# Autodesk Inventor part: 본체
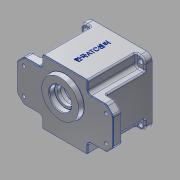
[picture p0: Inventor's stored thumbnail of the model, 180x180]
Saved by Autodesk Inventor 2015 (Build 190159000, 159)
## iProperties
Created: 2016-02
Part Number: 본체
Material: Aluminum 6061
Document SubType Name: Modeling
Designer: Administrator
Density: 2.7 g/cm^3
Appearance: Aluminum - Flat
Mass: 873.756 g
Surface Area: 761.195 cm^2
Volume: 323.613 cm^3
Author: Administrator
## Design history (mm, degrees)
sketch "Sketch2"
  geometry: L1 (-33, 30)-(-33, 47); L2 (-33, 47)-(33, 47); L3 (33, 47)-(33, 30); L4 (33, 30)-(57.929, 30); L5 (70, 17.929)-(70, -17.929); L6 (57.929, -30)-(33, -30); L7 (33, -30)-(33, -47); L8 (33, -47)-(-33, -47); L9 (-33, -47)-(-33, -30); L10 (-33, -30)-(-57.929, -30); L11 (-70, -17.929)-(-70, 17.929); L12 (-57.929, 30)-(-33, 30); L13 (-68.536, 21.464)-(-61.464, 28.536); L14 (-68.536, -21.464)-(-61.464, -28.536); L15 (61.464, -28.536)-(68.536, -21.464); L16 (68.536, 21.464)-(61.464, 28.536); A1 r 5 centre (57.929, -25) between (57.929, -30) and (61.464, -28.536); A2 r 5 centre (65, -17.929) between (68.536, -21.464) and (70, -17.929); A3 r 5 centre (65, -17.929) between (68.536, -21.464) and (70, -17.929); A4 r 5 centre (65, 17.929) between (70, 17.929) and (68.536, 21.464); A5 r 5 centre (57.929, 25) between (61.464, 28.536) and (57.929, 30); A6 r 5 centre (-57.929, 25) between (-57.929, 30) and (-61.464, 28.536); A7 r 5 centre (-65, 17.929) between (-68.536, 21.464) and (-70, 17.929); A8 r 5 centre (-57.929, -25) between (-61.464, -28.536) and (-57.929, -30); A9 r 5 centre (-65, -17.929) between (-70, -17.929) and (-68.536, -21.464); 13 further points
  constraints: 32 end point, 26 point on line, 18 point on circle, 18 tangent, 11 perpendicular, 9 centre point, 8 equal radius, 1 vertical
  dimensions: "d8" = 66 distance between parallel lines of L3 L1; "d9" = 66 distance between parallel lines of L7 L9; "d10" = 33 distance from line of point (0, 0) L1; "d11" = 33 distance from line of point (0, 0) L9; "d12" = 60 distance between parallel lines of L6 L4; "d13" = 60 distance of point (-70, -30) point (-70, 30); "d14" = 30 distance from line of point (0, 0) L12; "d15" = 30 distance from line of point (0, 0) L4; "d16" = 94 distance between parallel lines of L8 L2; "d17" = 47 distance from line of point (0, 0) L2; "d18" = 140 distance between parallel lines of L5 L11; "d19" = 70 distance from line of point (0, 0) L11; "d20" = 10 distance of point (-70, 20) point (-70, 30); "d21" = 10 distance of point (-60, 30) point (-70, 30) (= d20); "d22" = 10 distance of point (-70, -20) point (-70, -30) (= d20); "d23" = 10 distance of point (-60, -30) point (-70, -30) (= d22); "d24" = 10 distance of point (60, -30) point (70, -30) (= d20); "d25" = 10 distance of point (70, -20) point (70, -30) (= d24); "d26" = 10 distance of point (70, 20) point (70, 30) (= d20); "d27" = 10 distance of point (60, 30) point (70, 30) (= d26); "d127" = 5 radius of A1
extrude "Extrusion1" new body sketch "Sketch2" distance "d28" = 13; taper "d29" = 0 deg
sketch "Sketch3"
  geometry: L1 (39, 47)-(-39, 47); L2 (-47, 39)-(-47, -39); L3 (-39, -47)-(39, -47); L4 (47, -39)-(47, 39); L5 (47, 47)-(-47, -47); L6 (-47, 47)-(47, -47); A1 r 8 centre (39, -39) between (39, -47) and (47, -39); A2 r 8 centre (39, 39) between (47, 39) and (39, 47); A3 r 8 centre (-39, 39) between (-39, 47) and (-47, 39); A4 r 8 centre (-39, -39) between (-47, -39) and (-39, -47); 1 further point
  constraints: 12 end point, 8 point on circle, 8 point on line, 8 tangent, 4 centre point, 3 equal radius, 2 midpoint, 2 parallel, 1 horizontal, 1 perpendicular
  dimensions: "d30" = 94 distance of L5.end L6.end; "d31" = 94 distance of L6.start L5.end; "d32" = 8 radius of A1
extrude "Extrusion2" join sketch "Sketch3" distance "d33" = 67; taper "d34" = 0 deg
sketch "Sketch4"
  geometry: L1 (33, 30)-(47, 30) reference; L2 (47, 30)-(47, 39) reference; L3 (39, 47)-(33, 47) reference; L4 (33, 47)-(33, 30) reference; L5 (-47, 30)-(-33, 30) reference; L6 (-33, 30)-(-33, 47) reference; L7 (-33, 47)-(-39, 47) reference; L8 (-47, 39)-(-47, 30) reference; L9 (-33, -47)-(-33, -30) reference; L10 (-33, -30)-(-47, -30) reference; L11 (-47, -30)-(-47, -39) reference; L12 (-39, -47)-(-33, -47) reference; L13 (33, -30)-(33, -47) reference; L14 (33, -47)-(39, -47) reference; L15 (47, -39)-(47, -30) reference; L16 (47, -30)-(33, -30) reference; A1 r 8 centre (39, 39) between (47, 39) and (39, 47) reference; A2 r 8 centre (-39, 39) between (-39, 47) and (-47, 39) reference; A3 r 8 centre (-39, -39) between (-47, -39) and (-39, -47) reference; A4 r 8 centre (39, -39) between (39, -47) and (47, -39) reference; 1 further point
extrude "Extrusion3" cut sketch "Sketch4" distance "d35" = 57; taper "d36" = 0 deg
sketch "Sketch5"
  geometry: A1 r 36 centre (0, 0) between (-36, 0) and (36, 0); A2 r 4 centre (36, 0) between (35.852, 3.997) and (35.852, -3.997); A3 r 4 centre (-36, 0) between (-35.852, -3.997) and (-35.852, 3.997); A4 r 3.5 centre (35.722, -7.495) between (39.148, -8.214) and (35.778, -3.995); A5 r 3.5 centre (35.722, 7.495) between (35.778, 3.995) and (39.088, 8.456); A6 r 3.5 centre (-35.722, -7.495) between (-35.778, -3.995) and (-39.148, -8.214); A7 r 3.5 centre (-35.722, 7.495) between (-39.148, 8.214) and (-35.778, 3.995); A8 r 40 centre (0, 0) between (39.148, 8.214) and (-39.148, 8.214); A9 r 40 centre (0, 0) between (-39.148, -8.214) and (39.148, -8.214); 1 further point
  constraints: 27 point on circle, 9 centre point, 8 tangent, 2 coincident, 2 horizontal alignment
  dimensions: "d53" = 72 diameter of A1; "d54" = 4 radius of A2; "d55" = 4 radius of A3; "d56" = 3.5 radius of A4; "d57" = 3.5 radius of A5; "d58" = 3.5 radius of A6; "d60" = 40 radius of A9; "d61" = 40 radius of A8; "d62" = 3.5 radius of A7
extrude "Extrusion4" cut sketch "Sketch5" distance "d38" = 71; taper "d39" = 0 deg
sketch "Sketch6"
  geometry: C1 r 28 at (0, 11); 1 further point
  constraints: 1 centre point, 1 vertical alignment
  dimensions: "d40" = 56 diameter of C1; "d41" = 11 distance of point (0, 0) C1.centre
extrude "Extrusion5" join sketch "Sketch6" distance "d42" = 7; taper "d43" = -10 deg
sketch "Sketch10"
  geometry: C1 r 43 at (0, 0); 1 further point
  constraints: 1 centre point, 1 coincident
  dimensions: "d50" = 86 diameter of C1
extrude "Extrusion7" cut sketch "Sketch10" distance "d51" = 9; taper "d52" = 0 deg
sketch "Sketch11"
  geometry: A1 r 4 centre (36, 0) between (35.852, 3.997) and (35.852, -3.997) reference; A2 r 4 centre (-36, 0) between (-35.852, -3.997) and (-35.852, 3.997) reference; 3 further points
  constraints: 2 coincident
hole "Hole1" sketch "Sketch11" at (36, 0), (-36, 0) diameter "d63" = 3.242; stored, may be unused: countersink angle "d67" = 90 deg, drill point angle "d69" = 118 deg; dims "d64" = 7, "d65" = 4, "d66" = 2, "d68" = 9
sketch "Sketch12"
  geometry: C1 r 26.766 at (0, -11) reference; C2 r 21 at (0, -11); C3 r 15 at (0, 20); 1 further point
  constraints: 2 centre point, 1 coincident, 1 vertical alignment
  dimensions: "d72" = 21 radius of C2; "d73" = 15 radius of C3; "d74" = 20 distance of C3.centre point (0, 0)
extrude "Extrusion8" join sketch "Sketch12" distance "d75" = 7; taper "d76" = 0 deg
sketch "Sketch13"
  geometry: A1 r 15 centre (0, 20) between (8.978, 7.984) and (-8.978, 7.984) reference; 2 further points
  constraints: 1 coincident
hole "Hole2" sketch "Sketch13" at (0, 20) diameter "d77" = 19; stored, may be unused: countersink angle "d81" = 90 deg, drill point angle "d83" = 0 deg; dims "d78" = 7, "d79" = 22, "d80" = 7, "d82" = 8
sketch "Sketch14"
  geometry: A1 r 21 centre (0, -11) between (-8.978, 7.984) and (8.978, 7.984) reference; 2 further points
  constraints: 1 coincident
hole "Hole3" sketch "Sketch14" at (0, -11) diameter "d84" = 25; stored, may be unused: countersink angle "d88" = 90 deg, drill point angle "d90" = 0 deg; dims "d85" = 7, "d86" = 35, "d87" = 10, "d89" = 15
sketch "Sketch15"
  geometry: C1 r 26.766 at (0, 0) reference; 2 further points
  constraints: 1 coincident
hole "Hole4" sketch "Sketch15" at (0, 0) diameter "d91" = 32; stored, may be unused: countersink angle "d95" = 90 deg, drill point angle "d97" = 0 deg; dims "d92" = 7, "d93" = 35, "d94" = 10, "d96" = 8
sketch "Sketch17"
  geometry: 5 further points
  constraints: 2 horizontal alignment, 2 vertical alignment
  dimensions: "d102" = 120 distance of point (-60, -19) point (60, -19); "d103" = 60 horizontal distance of point (0, 0) point (60, -19); "d104" = 38 distance of point (-60, 19) point (-60, -19); "d105" = 19 vertical distance of point (0, 0) point (-60, -19)
hole "Hole5" sketch "Sketch17" at (60, -19), (60, 19), (-60, -19), (-60, 19) diameter "d106" = 5; stored, may be unused: countersink angle "d110" = 90 deg, drill point angle "d112" = 0 deg; dims "d107" = 7, "d108" = 9, "d109" = 4, "d111" = 8
sketch "Sketch18"
  geometry: 5 further points
  constraints: 2 horizontal alignment, 2 vertical alignment
  dimensions: "d113" = 80 distance of point (40, 40) point (-40, 40); "d114" = 40 horizontal distance of point (0, 0) point (-40, 40); "d115" = 80 distance of point (40, -40) point (40, 40); "d116" = 40 horizontal distance of point (0, 0) point (40, 40)
hole "Hole6" sketch "Sketch18" at (-40, 40), (-40, -40), (40, 40), (40, -40) diameter "d117" = 7; stored, may be unused: countersink angle "d121" = 90 deg, drill point angle "d123" = 0 deg; dims "d118" = 7, "d119" = 9, "d120" = 4, "d122" = 8
sketch "Sketch19" dims "d8" = 66, "d9" = 66, "d10" = 33, "d11" = 33, "d12" = 60, "d13" = 60, "d14" = 30, "d15" = 30, "d16" = 94, "d17" = 47, "d18" = 140, "d19" = 70, "d20" = 10, "d21" = 10 (= d20), "d22" = 10 (= d20), "d23" = 10 (= d22), "d24" = 10 (= d20), "d25" = 10 (= d24), "d26" = 10 (= d20), "d27" = 10 (= d26), "d127" = 5
  geometry: L1 (0, 0)-(66, 0) reference; L2 (-6, 80)-(72, 80) reference; 3 further points
  constraints: 1 midpoint, 1 vertical alignment, 1 other
  dimensions: "d124" = 40 distance from line of L2 point (33, 40)
emboss "Emboss1" sketch "Sketch19" dims "d8" = 66, "d9" = 66, "d10" = 33, "d11" = 33, "d12" = 60, "d13" = 60, "d14" = 30, "d15" = 30, "d16" = 94, "d17" = 47, "d18" = 140, "d19" = 70, "d20" = 10, "d21" = 10 (= d20), "d22" = 10 (= d20), "d23" = 10 (= d22), "d24" = 10 (= d20), "d25" = 10 (= d24), "d26" = 10 (= d20), "d27" = 10 (= d26), "d125" = 0.5, "d126" = 0, "d127" = 5
fillet "Fillet1" dims "d128" = 5
chamfer "Chamfer1" distance "d129" = 1; stored, may be unused: second distance "d130" = 2, angle "d131" = 45 deg
fillet "Fillet2" dims "d132" = 0.3
fillet "Fillet3" dims "d133" = 2
fillet "Fillet4" dims "d134" = 2
sketch "Sketch20"
  geometry: L1 (-31, 47)-(31, 47) reference; L2 (-33, 35)-(-33, 45) reference; L3 (-57.929, 30)-(-38, 30) reference; L4 (-68.536, 21.464)-(-61.464, 28.536) reference; L5 (-70, -17.929)-(-70, 17.929) reference; L6 (-61.464, -28.536)-(-68.536, -21.464) reference; L7 (-38, -30)-(-57.929, -30) reference; L8 (-33, -45)-(-33, -35) reference; L9 (31, -47)-(-31, -47) reference; L10 (33, 45)-(33, 35) reference; L11 (38, 30)-(57.929, 30) reference; L12 (61.464, 28.536)-(68.536, 21.464) reference; L13 (70, 17.929)-(70, -17.929) reference; L14 (68.536, -21.464)-(61.464, -28.536) reference; L15 (57.929, -30)-(38, -30) reference; L16 (33, -35)-(33, -45) reference; L17 (31, 46)-(-31, 46); L18 (-32, 45)-(-32, 35); L19 (-38, 29)-(-57.929, 29); L20 (-60.757, 27.828)-(-67.828, 20.757); L21 (-69, 17.929)-(-69, -17.929); L22 (-67.828, -20.757)-(-60.757, -27.828); L23 (-57.929, -29)-(-38, -29); L24 (-32, -35)-(-32, -45); L25 (-31, -46)-(31, -46); L26 (32, -45)-(32, -35); L27 (38, -29)-(57.929, -29); L28 (60.757, -27.828)-(67.828, -20.757); L29 (69, -17.929)-(69, 17.929); L30 (67.828, 20.757)-(60.757, 27.828); L31 (57.929, 29)-(38, 29); L32 (32, 35)-(32, 45); A1 r 2 centre (-31, 45) between (-31, 47) and (-33, 45) reference; A2 r 5 centre (-38, 35) between (-38, 30) and (-33, 35) reference; A3 r 5 centre (-57.929, 25) between (-57.929, 30) and (-61.464, 28.536) reference; A4 r 5 centre (-65, 17.929) between (-68.536, 21.464) and (-70, 17.929) reference; A5 r 5 centre (-65, -17.929) between (-70, -17.929) and (-68.536, -21.464) reference; A6 r 5 centre (-57.929, -25) between (-61.464, -28.536) and (-57.929, -30) reference; A7 r 5 centre (-38, -35) between (-33, -35) and (-38, -30) reference; A8 r 2 centre (-31, -45) between (-33, -45) and (-31, -47) reference; A9 r 5 centre (38, 35) between (33, 35) and (38, 30) reference; A10 r 2 centre (31, 45) between (33, 45) and (31, 47) reference; A11 r 5 centre (57.929, 25) between (61.464, 28.536) and (57.929, 30) reference; A12 r 5 centre (65, 17.929) between (70, 17.929) and (68.536, 21.464) reference; A13 r 5 centre (65, -17.929) between (68.536, -21.464) and (70, -17.929) reference; A14 r 5 centre (57.929, -25) between (57.929, -30) and (61.464, -28.536) reference; A15 r 5 centre (38, -35) between (38, -30) and (33, -35) reference; A16 r 2 centre (31, -45) between (31, -47) and (33, -45) reference; A17 r 1 centre (-31, 45) between (-31, 46) and (-32, 45); A18 r 6 centre (-38, 35) between (-38, 29) and (-32, 35); A19 r 4 centre (-57.929, 25) between (-57.929, 29) and (-60.757, 27.828); A20 r 4 centre (-65, 17.929) between (-67.828, 20.757) and (-69, 17.929); A21 r 4 centre (-65, -17.929) between (-69, -17.929) and (-67.828, -20.757); A22 r 4 centre (-57.929, -25) between (-60.757, -27.828) and (-57.929, -29); A23 r 6 centre (-38, -35) between (-32, -35) and (-38, -29); A24 r 1 centre (-31, -45) between (-32, -45) and (-31, -46); A25 r 1 centre (31, -45) between (31, -46) and (32, -45); A26 r 6 centre (38, -35) between (38, -29) and (32, -35); A27 r 4 centre (57.929, -25) between (57.929, -29) and (60.757, -27.828); A28 r 4 centre (65, -17.929) between (67.828, -20.757) and (69, -17.929); A29 r 4 centre (65, 17.929) between (69, 17.929) and (67.828, 20.757); A30 r 4 centre (57.929, 25) between (60.757, 27.828) and (57.929, 29); A31 r 6 centre (38, 35) between (32, 35) and (38, 29); A32 r 1 centre (31, 45) between (32, 45) and (31, 46); 1 further point
  constraints: 32 end point, 32 point on circle, 16 centre point, 31 other
  dimensions: "d135" = 1 distance between parallel lines of L1 L17
extrude "Extrusion9" cut sketch "Sketch20" distance "d136" = 1; taper "d137" = 0 deg
fillet "Fillet5" dims "d138" = 2
fillet "Fillet6" dims "d139" = 3
fillet "Fillet7" dims "d140" = 2
fillet "Fillet8" dims "d141" = 0.3
body "Solid1"
node "Projected Loop1"
node "Projected Loop2"
node "Projected Loop3"
node "Projected Loop4"
other parameters: "d59" = 3.5
